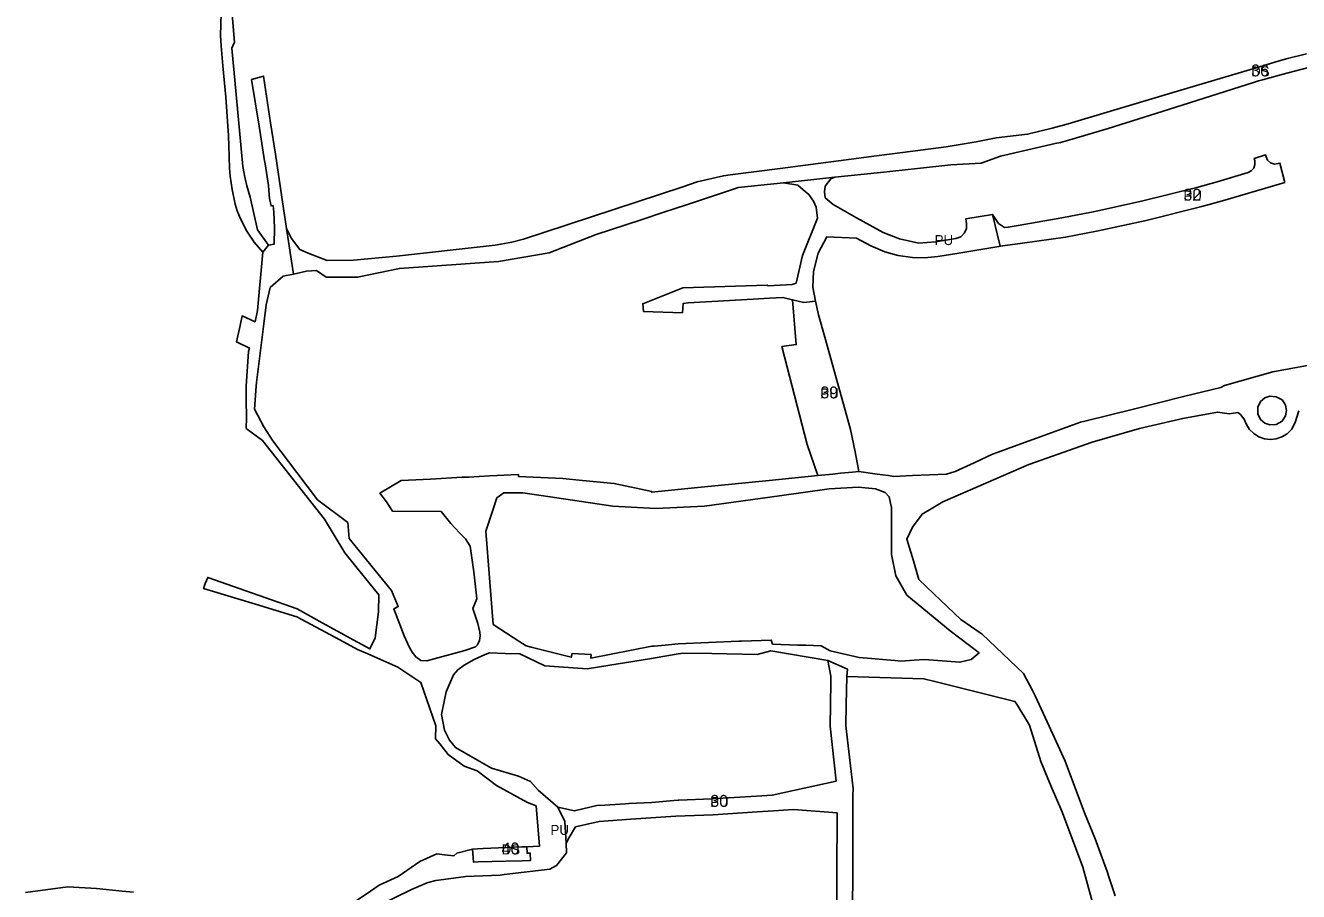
# Model space of a CAD drawing. Extents: x -535435 to -532834, y -1165802 to -1163866.
# Drawn here: x -534750 to -534109, y -1165135 to -1164698 of the extents above; entities that cross this region are included whole.
import ezdxf

# ---------------------------------------------------------------- set-up
doc = ezdxf.new("R2010")
doc.units = 0
for name, color, linetype in [('90320023', 7, 'Continuous'), ('90450013', 7, 'Continuous'), ('90450023', 7, 'Continuous'), ('ID_navrh', 7, 'Continuous')]:
    doc.layers.add(name, color=color, linetype=linetype)

msp = doc.modelspace()

# ---------------------------------------------------------------- linework, layer by layer
at = {"layer": '90320023'}
for points in [[(-534645.38, -1164692.752), (-534644.26, -1164706.72), (-534645.604, -1164709.726), (-534643.475, -1164733.089), (-534640.098, -1164769.323), (-534639.373, -1164772.852), (-534639.176, -1164773.814), (-534638.852, -1164775.393), (-534638.064, -1164779.14), (-534636.46, -1164784.72), (-534632.72, -1164801.19), (-534627.21, -1164808.9), (-534629.933, -1164812.5), (-534634.384, -1164807.473), (-534638.138, -1164801.982), (-534641.201, -1164795.663), (-534642.853, -1164791.65), (-534643.958, -1164788.253), (-534645.397, -1164780.979), (-534646.536, -1164774.156), (-534646.876, -1164770.138), (-534646.997, -1164764.497), (-534647.322, -1164753.718), (-534648.645, -1164734.35), (-534650.184, -1164718.674), (-534651.057, -1164708.531), (-534651.253, -1164703.409), (-534650.975, -1164692.251)], [(-534102.862, -1164719.219), (-534114.467, -1164722.35), (-534126.834, -1164725.687), (-534128.725, -1164726.223), (-534131.259, -1164726.941), (-534174.083, -1164740.654), (-534204.47, -1164750.16), (-534219.283, -1164754.495), (-534222.586, -1164755.485), (-534228.446, -1164757.195), (-534231.063, -1164757.758), (-534258.606, -1164764.075), (-534268.47, -1164767.68), (-534283.7, -1164768.52), (-534300.47, -1164770.31), (-534319.12, -1164772.3), (-534342.086, -1164774.76), (-534367.86, -1164777.52), (-534390.78, -1164779.97), (-534393.08, -1164780.73), (-534416.78, -1164788.57), (-534428.15, -1164792.33), (-534439.58, -1164796.11), (-534462.18, -1164803.59), (-534485.79, -1164812.88), (-534511.37, -1164817.22), (-534561.27, -1164820.66), (-534582.32, -1164825.13), (-534598.14, -1164825.08), (-534603.04, -1164821.677), (-534608.112, -1164822.093), (-534614.56, -1164823.48), (-534618.03, -1164800.56), (-534615.55, -1164805.6), (-534611.449, -1164811.194), (-534607.18, -1164812.97), (-534597.567, -1164816.729), (-534584.381, -1164816.448), (-534562.681, -1164814.447), (-534513.084, -1164808.974), (-534510.13, -1164808.51), (-534504.58, -1164807.36), (-534498.81, -1164805.87), (-534488.479, -1164802.488), (-534464.631, -1164794.65), (-534418.651, -1164779.505), (-534411.44, -1164777.13), (-534398.19, -1164773.99), (-534394.776, -1164773.547), (-534369.617, -1164770.285), (-534321.12, -1164763.995), (-534302.826, -1164761.623), (-534286.069, -1164759.45), (-534270.957, -1164756.824), (-534260.885, -1164754.965), (-534245.02, -1164753.04), (-534232.713, -1164750.025), (-534224.583, -1164747.891), (-534221.258, -1164746.894), (-534175.745, -1164733.28), (-534166.143, -1164730.401), (-534130.015, -1164719.567), (-534118.867, -1164716.27), (-534114.899, -1164715.096), (-534104.663, -1164712.55)]]:
    msp.add_lwpolyline(points, dxfattribs=at)
msp.add_lwpolyline([(-534523.98, -1165119.71), (-534524.4, -1165113.2), (-534521.96, -1165113.08), (-534519.03, -1165112.95), (-534499.64, -1165112.1), (-534497.04, -1165112.02), (-534496.95, -1165115.27), (-534495.36, -1165115.23), (-534495.25, -1165118.92), (-534499.45, -1165119.04), (-534507.64, -1165119.26), (-534521.53, -1165119.64)], close=True, dxfattribs=at)
at = {"layer": '90450013'}
for points in [[(-534590.09, -1165143.97), (-534575.87, -1165134.421), (-534571.4, -1165131.42), (-534561.87, -1165126.95), (-534551, -1165119.46), (-534542.44, -1165115.58), (-534538.48, -1165116.07), (-534533.82, -1165116.64), (-534532.37, -1165115.29), (-534524.4, -1165113.2), (-534523.98, -1165119.71), (-534521.53, -1165119.64), (-534507.64, -1165119.26), (-534499.45, -1165119.04), (-534495.25, -1165118.92), (-534495.36, -1165115.23), (-534496.95, -1165115.27), (-534497.04, -1165112.02), (-534490.797, -1165111.763), (-534492.418, -1165091.462), (-534496.832, -1165089.669), (-534512.37, -1165081.09), (-534522.06, -1165073.71), (-534528.58, -1165071.39), (-534536.786, -1165065.584), (-534540.96, -1165060.2), (-534543.04, -1165057.57), (-534542.87, -1165051.15), (-534550.39, -1165029.21), (-534562.04, -1165021.58), (-534577.2, -1165014.853), (-534582.3, -1165012.59), (-534591.32, -1165007.75), (-534612.88, -1164996.18), (-534633.77, -1164989.84), (-534642.59, -1164987.17), (-534659.81, -1164981.95), (-534659.02, -1164979.39), (-534657.76, -1164976.32), (-534612.8, -1164992.22), (-534600.2, -1164999.12), (-534590.54, -1165004.41), (-534586.35, -1165006.69), (-534576.08, -1165012.33), (-534573.45, -1165006.71), (-534571.86, -1164993.7), (-534571.66, -1164985.07), (-534583.16, -1164970.86), (-534588.73, -1164964), (-534599.05, -1164947.01), (-534630.14, -1164907.3), (-534638.33, -1164901.25), (-534638.31, -1164895.93), (-534638.46, -1164886.69), (-534638.46, -1164879.942), (-534637.156, -1164862.496), (-534636.791, -1164860.825), (-534643.23, -1164857.71), (-534641.49, -1164849.43), (-534640.463, -1164844.555), (-534633.89, -1164847.539), (-534632.65, -1164841.86), (-534629.933, -1164812.5), (-534627.21, -1164808.9), (-534624.26, -1164808.39), (-534624.07, -1164800.22), (-534624.44, -1164792.41), (-534624.82, -1164789.03), (-534625.82, -1164789.15), (-534626.73, -1164785.43), (-534626.84, -1164783.65), (-534627.14, -1164778.96), (-534628.86, -1164767.99), (-534628.99, -1164767.2), (-534629.1, -1164766.51), (-534631.92, -1164749.04), (-534635.7, -1164725.53), (-534629.67, -1164723.78), (-534626.11, -1164747.28), (-534623.71, -1164763.1), (-534619.57, -1164790.4), (-534618.03, -1164800.56), (-534614.56, -1164823.48), (-534619.84, -1164824.52), (-534626.3, -1164830.31), (-534628.39, -1164839.07), (-534629.49, -1164848.51), (-534633.15, -1164878.09), (-534633.32, -1164879.93), (-534634.21, -1164891.59), (-534629.53, -1164900.39), (-534624.92, -1164907.57), (-534612.91, -1164923.42), (-534602.43, -1164937.26), (-534587.3, -1164948.74), (-534586.6, -1164956.69), (-534571.32, -1164975.54), (-534565.31, -1164982.96), (-534561.82, -1164991.02), (-534564.1, -1164992.18), (-534558.89, -1165005.68), (-534556.42, -1165011.31), (-534554.89, -1165013.98), (-534553.07, -1165016.4), (-534550.49, -1165018.12), (-534547.38, -1165018.35), (-534528.3, -1165013.15), (-534522.94, -1165011.32), (-534521.91, -1165010.32), (-534520.93, -1165008.08), (-534520.65, -1165005.82), (-534520.8, -1165003.96), (-534521.78, -1164999.46), (-534524.23, -1164991.91), (-534522.25, -1164987.18), (-534523.76, -1164973.56), (-534525.63, -1164960.55), (-534528.03, -1164956.95), (-534530.94, -1164953.79), (-534535.29, -1164949.09), (-534540.3, -1164943.15), (-534564.69, -1164943.03), (-534567.81, -1164938.28), (-534571.09, -1164933.92), (-534560.34, -1164927.43), (-534545.54, -1164926.82), (-534529.67, -1164925.9), (-534529.29, -1164925.89), (-534526.26, -1164925.74), (-534515.85, -1164925.23), (-534501.38, -1164924.52), (-534501.29, -1164925.46), (-534479.05, -1164926.51), (-534469.12, -1164927.47), (-534453.19, -1164929.01), (-534434.25, -1164932.97), (-534434.37, -1164933.46), (-534409.31, -1164930.93), (-534375.06, -1164927.47), (-534350.56, -1164925), (-534342.99, -1164924.23), (-534339.283, -1164923.854), (-534333.22, -1164923.24), (-534329.95, -1164922.91), (-534320.81, -1164924.23), (-534315.05, -1164925.05), (-534312.36, -1164925.44), (-534302.96, -1164925.05), (-534285.82, -1164924.34), (-534281.43, -1164922.93), (-534271.94, -1164918.56), (-534268, -1164916.74), (-534262.64, -1164914.28), (-534259.85, -1164913.26), (-534253.91, -1164911.1), (-534240.59, -1164906.25), (-534218.39, -1164898.16), (-534216.19, -1164897.61), (-534191.06, -1164891.36), (-534166.53, -1164885.27), (-534147.77, -1164880.61), (-534145.84, -1164879.67), (-534121.57, -1164872.72), (-534096.94, -1164868.25)], [(-534108.42, -1164892.42), (-534110.31, -1164898.33), (-534112.2, -1164901.85), (-534114.35, -1164903.98), (-534117.01, -1164905.53), (-534119.83, -1164906.52), (-534122.74, -1164906.88), (-534125.82, -1164906.5), (-534128.69, -1164905.48), (-534131.19, -1164903.88), (-534133.26, -1164901.76), (-534134.79, -1164899.23), (-534136.05, -1164896.57), (-534136.17, -1164896.41), (-534137.85, -1164894.21), (-534139.15, -1164893.18), (-534143.59, -1164893.98), (-534149.48, -1164893.03), (-534166.92, -1164896.21), (-534188.71, -1164901.35), (-534212.46, -1164908.12), (-534244.36, -1164919.45), (-534287.71, -1164938.27), (-534292.74, -1164941.26), (-534298.12, -1164944.44), (-534302.89, -1164950.93), (-534305.74, -1164957.13), (-534302.49, -1164968.05), (-534299.71, -1164977.41), (-534292.25, -1164984.51), (-534278.67, -1164997.45), (-534268.88, -1165004.18), (-534267.81, -1165004.92), (-534247.06, -1165024.76), (-534242.54, -1165033.34), (-534241.2, -1165036.01), (-534234.19, -1165051.24), (-534226.11, -1165068.82), (-534216.42, -1165094.93), (-534211.01, -1165107.94), (-534204.94, -1165124.43), (-534203.92, -1165127.62), (-534201, -1165136.72)], [(-534212.54, -1165139.35), (-534217.22, -1165122.23), (-534222.38, -1165108.41), (-534227.74, -1165094.09), (-534233.08, -1165081.58), (-534238.41, -1165069.05), (-534244.03, -1165050.78), (-534250.52, -1165040.21), (-534251.41, -1165038.78), (-534291.71, -1165028.75), (-534297.22, -1165027.38), (-534336.09, -1165026.21), (-534335.684, -1165022.47), (-534345.52, -1165018.15), (-534374.22, -1165013.39), (-534381.21, -1165015.12), (-534403.97, -1165014.71), (-534418.3, -1165014.45), (-534420.99, -1165014.89), (-534435.41, -1165017.27), (-534451.2, -1165019.87), (-534466.76, -1165022.45), (-534488.01, -1165020.91), (-534500.56, -1165014.81), (-534508.03, -1165014.6), (-534515.85, -1165014.39), (-534518.13, -1165015.17), (-534523.64, -1165017.68), (-534528.72, -1165020.51), (-534531.91, -1165022.8), (-534534.04, -1165025.41), (-534537.78, -1165033.97), (-534538.58, -1165038), (-534540.03, -1165045.35), (-534538.55, -1165053.24), (-534536.12, -1165058.39), (-534533.08, -1165062.06), (-534523.11, -1165067.68), (-534514.83, -1165072.36), (-534501.27, -1165076.38), (-534495.29, -1165079.16), (-534491.48, -1165083.48), (-534481.55, -1165092.073), (-534477.91, -1165099.28), (-534477.365, -1165110.203), (-534477.12, -1165115.1), (-534482.11, -1165121.5), (-534485.47, -1165123.31), (-534508.47, -1165126.04), (-534510.46, -1165126.27), (-534527.96, -1165127.06), (-534529.03, -1165127.13), (-534542.89, -1165128.92), (-534546.81, -1165129.93), (-534548.1, -1165130.49), (-534555.22, -1165133.48), (-534572.34, -1165142)], [(-534749.51, -1165134.97), (-534728.232, -1165132.152), (-534713.679, -1165132.97), (-534700.81, -1165134.426), (-534695.14, -1165134.964)]]:
    msp.add_lwpolyline(points, dxfattribs=at)
for points in [[(-534342.086, -1164774.76), (-534344.157, -1164775.523), (-534346.921, -1164779.295), (-534347.251, -1164782.065), (-534346.921, -1164785.052), (-534342.89, -1164788.411), (-534331.086, -1164795.189), (-534317.684, -1164802.586), (-534309.479, -1164805.759), (-534299.79, -1164807.88), (-534291.34, -1164807.29), (-534281.07, -1164805.63), (-534278.66, -1164804.69), (-534276.78, -1164802.81), (-534275.85, -1164800.57), (-534275.8, -1164798.11), (-534276.18, -1164795.73), (-534262.71, -1164793.42), (-534258.75, -1164809.52), (-534259.51, -1164809.65), (-534280.7, -1164813.17), (-534290.15, -1164814.7), (-534296.93, -1164815.35), (-534303.02, -1164815.23), (-534310.16, -1164814.2), (-534316.94, -1164812.28), (-534324, -1164809.24), (-534331.17, -1164805.49), (-534346.02, -1164804.74), (-534350.53, -1164813.01), (-534352.88, -1164822.3), (-534353.07, -1164830.03), (-534351.84, -1164837.24), (-534357.64, -1164837.76), (-534363.299, -1164836.431), (-534368.16, -1164835.29), (-534375.03, -1164835.57), (-534383.14, -1164836.16), (-534415.92, -1164838.06), (-534418.37, -1164838.3), (-534418.77, -1164843.03), (-534438.32, -1164842.42), (-534438.72, -1164838.43), (-534418.52, -1164830.41), (-534376.12, -1164829.05), (-534375.55, -1164829.48), (-534363.61, -1164828.81), (-534361.562, -1164828.03), (-534358.41, -1164814.11), (-534350.811, -1164795.268), (-534351.435, -1164789.841), (-534352.772, -1164786.79), (-534355.088, -1164783.449), (-534357.919, -1164781.042), (-534360.697, -1164778.681), (-534367.86, -1164777.52)], [(-534129.089, -1164891.38), (-534129.089, -1164893.957), (-534127.712, -1164896.82), (-534125.618, -1164898.633), (-534123.001, -1164899.539), (-534119.833, -1164899.301), (-534116.941, -1164897.631), (-534115.15, -1164895.006), (-534114.627, -1164892.287), (-534115.15, -1164889.567), (-534115.564, -1164888.961), (-534116.941, -1164886.943), (-534119.833, -1164885.273), (-534123.001, -1164885.034), (-534125.618, -1164885.941), (-534127.712, -1164887.754), (-534129.089, -1164890.617)], [(-534494.86, -1165011.42), (-534474.77, -1165016.57), (-534474.29, -1165014.68), (-534464.79, -1165015.17), (-534464.85, -1165016.92), (-534434.11, -1165010.99), (-534433.05, -1165010.9), (-534427.49, -1165010.4), (-534420.92, -1165009.8), (-534390.4, -1165008.5), (-534389.11, -1165008.45), (-534374.04, -1165007.87), (-534373.42, -1165009.91), (-534360.64, -1165010.37), (-534356.63, -1165010.51), (-534348.99, -1165010.79), (-534344.37, -1165013.33), (-534329.82, -1165016.63), (-534323.68, -1165017.15), (-534316.13, -1165017.8), (-534311.71, -1165018.18), (-534308.77, -1165018.44), (-534302.11, -1165018.01), (-534296.99, -1165017.68), (-534279.05, -1165019.05), (-534273.424, -1165017.68), (-534269.44, -1165014.34), (-534283.92, -1165003.31), (-534305.86, -1164985.22), (-534311.34, -1164975.55), (-534313.47, -1164964.73), (-534313.54, -1164953.57), (-534313.54, -1164941.084), (-534313.98, -1164938.937), (-534314.652, -1164935.656), (-534316.655, -1164933.547), (-534321.609, -1164931.634), (-534330.148, -1164930.912), (-534344.906, -1164931.755), (-534369.994, -1164935.234), (-534407.72, -1164940.465), (-534432.188, -1164941.664), (-534453.798, -1164940.399), (-534489.849, -1164935.129), (-534499.188, -1164933.763), (-534508.626, -1164933.758), (-534512.197, -1164936.183), (-534513.989, -1164941.981), (-534517.7, -1164953.01), (-534514.1, -1165000.01), (-534500.57, -1165008.73), (-534499.22, -1165009.6), (-534497.44, -1165010.75)]]:
    msp.add_lwpolyline(points, close=True, dxfattribs=at)
at = {"layer": '90450023'}
for points in [[(-534115.534, -1164777.344), (-534146.945, -1164786.623), (-534157.264, -1164789.477), (-534185.409, -1164796.553), (-534207.117, -1164801.299), (-534210.381, -1164801.967), (-534225.907, -1164804.981), (-534247.597, -1164807.979), (-534258.75, -1164809.52), (-534262.71, -1164793.42), (-534259.633, -1164798), (-534256.663, -1164800.012), (-534254.781, -1164799.959), (-534249.823, -1164799.102), (-534227.745, -1164795.151), (-534212.925, -1164792.28), (-534209.638, -1164791.608), (-534187.684, -1164786.815), (-534159.868, -1164779.822), (-534149.667, -1164777.001), (-534134.021, -1164772.377), (-534132.422, -1164771.562), (-534131.152, -1164770.104), (-534130.545, -1164768.267), (-534130.659, -1164766.477), (-534130.976, -1164765.221), (-534125.218, -1164763.519), (-534124.996, -1164764.397), (-534124.195, -1164766.096), (-534122.671, -1164767.453), (-534120.726, -1164768.073), (-534118.856, -1164767.895), (-534117.988, -1164767.638)], [(-534351.84, -1164837.24), (-534350.27, -1164844.02), (-534347.133, -1164855.259), (-534337.71, -1164889.02), (-534334.14, -1164901.79), (-534331.9, -1164913.07), (-534329.95, -1164922.91), (-534333.22, -1164923.24), (-534339.283, -1164923.854), (-534342.99, -1164924.23), (-534350.56, -1164925), (-534355.92, -1164909.3), (-534368.709, -1164859.957), (-534361.448, -1164859.007), (-534363.299, -1164836.431), (-534357.64, -1164837.76)]]:
    msp.add_lwpolyline(points, close=True, dxfattribs=at)
msp.add_lwpolyline([(-534341.17, -1165157.05), (-534340.945, -1165094.96), (-534362.94, -1165093.25), (-534372.898, -1165093.976), (-534381.169, -1165094.484), (-534403.258, -1165095.841), (-534422.065, -1165096.672), (-534444.708, -1165098.163), (-534456.213, -1165098.932), (-534460.621, -1165099.221), (-534467.426, -1165100.793), (-534472.584, -1165101.984), (-534475.74, -1165107.41), (-534477.365, -1165110.203), (-534477.91, -1165099.28), (-534481.55, -1165092.073), (-534473.085, -1165093.889), (-534468.89, -1165092.92), (-534461.79, -1165091.28), (-534457.81, -1165091.02), (-534447.57, -1165090.34), (-534445.83, -1165090.22), (-534434.26, -1165089.65), (-534423.1, -1165088.71), (-534420.94, -1165088.56), (-534420.53, -1165088.55), (-534403.97, -1165087.87), (-534381.51, -1165086.49), (-534373.53, -1165086), (-534341.356, -1165078.895), (-534344.452, -1165051.282), (-534344.146, -1165029.232), (-534344.089, -1165026.065), (-534345.52, -1165018.15), (-534335.684, -1165022.47), (-534336.09, -1165026.21), (-534336.35, -1165040.51), (-534336.45, -1165051.12), (-534333.89, -1165074.023), (-534332.91, -1165082.796), (-534332.918, -1165086.143), (-534332.957, -1165098.525), (-534333.007, -1165112.189), (-534333.054, -1165125.224), (-534333.121, -1165143.491)], dxfattribs=at)

# ---------------------------------------------------------------- texts
at = {"layer": '90320023'}
for rotation, p in [(360, (-534132.4645, -1164723.936)), (359.9999999, (-534509.7846, -1165115.865))]:
    msp.add_text('DS', height=5, rotation=rotation, dxfattribs=at).set_placement(p)
at = {"layer": '90450013'}
for rotation, p in [(360, (-534291.7817, -1164808.895)), (0.0000001, (-534485.199, -1165106.0397))]:
    msp.add_text('PU', height=5, rotation=rotation, dxfattribs=at).set_placement(p)
at = {"layer": '90450023'}
for rotation, p in [(360, (-534166.5516, -1164786.5195)), (0, (-534349.3295, -1164886.1322)), (360, (-534404.724, -1165091.9034))]:
    msp.add_text('PU', height=5, rotation=rotation, dxfattribs=at).set_placement(p)
at = {"layer": 'ID_navrh'}
for s, rotation, p in [('36', 360, (-534132.4645, -1164723.936)), ('32', 0, (-534166.5516, -1164786.5195)), ('39', 0, (-534349.3295, -1164886.1322)), ('30', 0, (-534404.724, -1165091.9034)), ('40', 359.9999999, (-534509.7846, -1165115.865))]:
    msp.add_text(s, height=6, rotation=rotation, dxfattribs=at).set_placement(p)

doc.saveas('drawing.dxf')
